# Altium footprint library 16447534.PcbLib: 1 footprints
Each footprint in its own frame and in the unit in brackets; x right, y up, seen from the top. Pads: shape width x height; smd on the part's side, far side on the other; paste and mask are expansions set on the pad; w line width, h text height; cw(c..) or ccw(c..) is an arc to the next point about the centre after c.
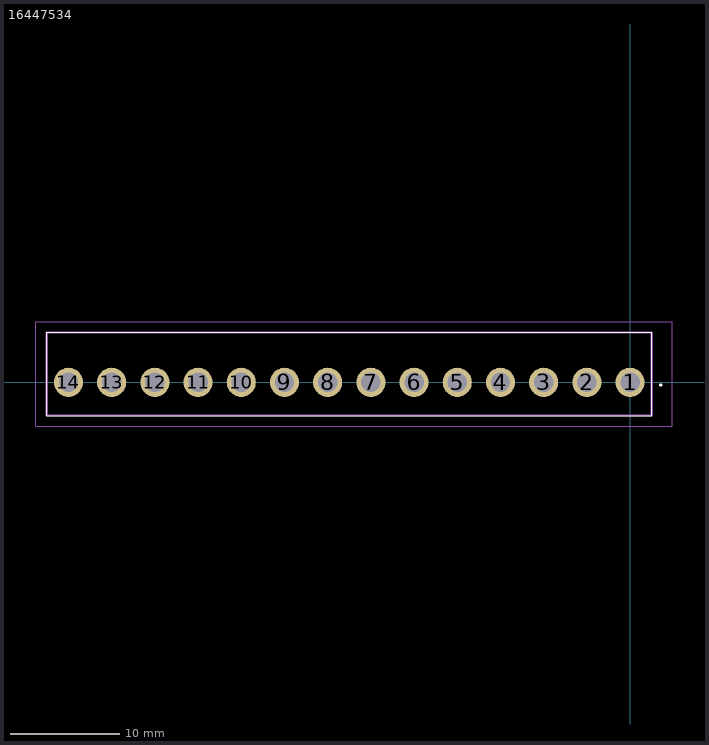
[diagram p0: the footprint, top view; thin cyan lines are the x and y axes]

## 16447534 [mm]
pads (14):
  round 2.67 hole 1.78: 1(0,0) 2(-3.96,0) 3(-7.92,0) 4(-11.88,0) 5(-15.84,0) 6(-19.8,0) 7(-23.76,0) 8(-27.72,0) 9(-31.68,0) 10(-35.64,0) 11(-39.6,0) 12(-43.56,0) 13(-47.52,0) 14(-51.48,0)
Top Overlay:
  lines w0.1: -53.475,-3.048 -53.475,4.572 1.98,4.572 1.98,-3.048 -53.475,-3.048
  lines w0.2: 2.76,-0.238 cw(c2.81,-0.238) 2.86,-0.238 cw(c2.81,-0.238) 2.76,-0.238
Mechanical 15:
  lines w0.2: -53.475,-3.048 -53.475,4.572 1.995,4.572 1.995,-3.048 -53.475,-3.048
Mechanical 20:
  lines w0.1: -54.475,-4.048 -54.475,5.572 3.86,5.572 3.86,-4.048 -54.475,-4.048
3D body "1-644753-4.stp": height 5.8, standoff -4.65, extent -10,-3.376 10,3.376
